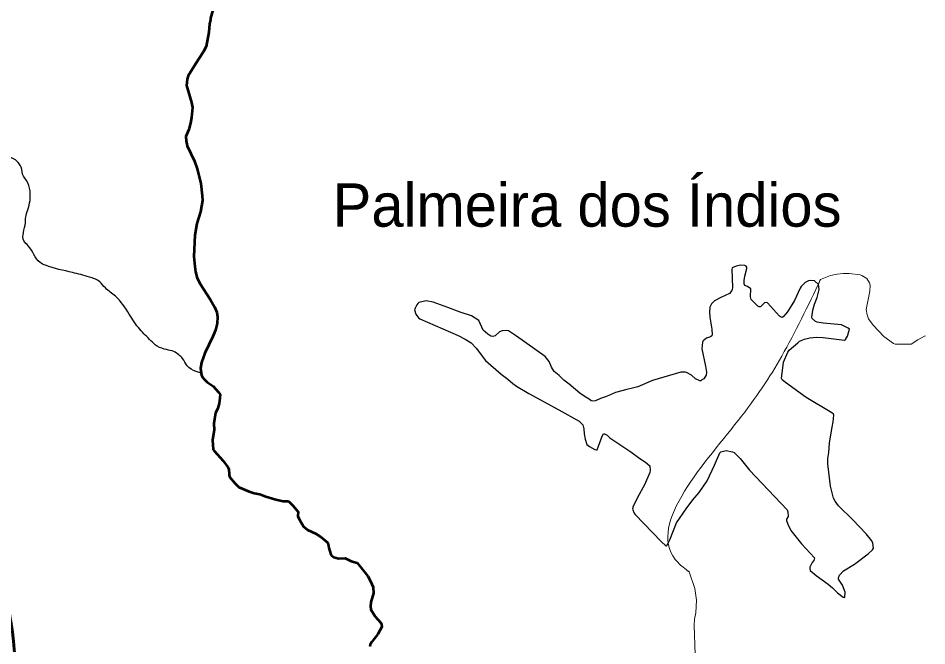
# Model space of a CAD drawing. Extents: x -1643653 to 4543381, y 1624270 to 13878484.
# Drawn here: x 752066 to 762553, y 8956206 to 8963451 of the extents above; entities that cross this region are included whole.
import ezdxf

# ---------------------------------------------------------------- set-up
doc = ezdxf.new("R2010")
doc.units = 0
doc.header["$LTSCALE"] = 160
doc.linetypes.add('MEDIUM_DASHED', pattern=[4.5, 3, -1.5])
for name, color, linetype, lineweight in [('10', 7, 'MEDIUM_DASHED', 60), ('14', 7, 'Continuous', 13), ('21', 7, 'Continuous', 25), ('24', 7, 'Continuous', 25), ('60', 7, 'Continuous', 13)]:
    doc.layers.add(name, color=color, linetype=linetype, lineweight=lineweight)
doc.layers.add('41', color=7, linetype='Continuous')

msp = doc.modelspace()

# ---------------------------------------------------------------- linework, layer by layer
at = {"layer": '10'}
for points in [[(751718.9, 8957290.2), (751531.6, 8957712.2), (750995.8, 8957861.4), (750836, 8958259.9), (750739.1, 8958501.4), (750810.6, 8958803), (750701.7, 8959043.4), (750649.5, 8959158.5), (750585.8, 8959273.1), (750522.6, 8959379.2), (750416.4, 8959557.6), (750245.2, 8959714.4), (750142.1, 8959894), (750059.8, 8960037.4), (750424.3, 8960195.8), (750388.3, 8960341.7), (750306, 8960675.5), (749757.2, 8960933.4), (749694.4, 8961281.9), (749657.1, 8961488.8), (749737.2, 8961760.6), (749694.4, 8961975.8), (749670.2, 8962097.1), (749510.2, 8962210.1), (749537.7, 8962334), (749613.3, 8962675.1), (749758.5, 8963019.6), (749851.1, 8963363.7), (749964, 8963783.7), (750022.5, 8964223.4), (750164.5, 8964639.7), (750243.4, 8964871.2), (750497.6, 8964991.5), (750634.5, 8965199.3), (750728.3, 8965341.6), (750833.7, 8965482.3), (750858.4, 8965647), (750892.9, 8965877.2), (750782, 8966109.4), (750768.8, 8966340.9), (750760.8, 8966481.8), (750668.1, 8966638.3), (750791.2, 8966766.2), (750923.4, 8966903.6), (751072.8, 8966882.1), (751216.6, 8966934), (751537.1, 8967049.7), (751840, 8967247.2), (752179.1, 8967269.8), (752291, 8967277.3), (752403, 8967284.8), (752514.9, 8967292.2), (752738.7, 8967307.2), (752962.6, 8967322.1), (753186.4, 8967337), (753247.3, 8967341.1), (753307.9, 8967370.8), (753353.8, 8967411.3)], [(752064, 8949931.3), (752226.2, 8950099), (752371.1, 8950281.5), (752484, 8950494.8), (752727.4, 8950954.4), (752832, 8951444.1), (752990, 8951926.7), (753136.7, 8952374.9), (753359.2, 8952845.2), (753347.9, 8953290.8), (753342, 8953522.6), (753008.5, 8953646.6), (752804.9, 8953784.5), (752471.5, 8954010.4), (751900.3, 8953804.2), (751669.5, 8954179.5), (751384.3, 8954643.3), (752099.3, 8955128.6), (752064.4, 8955611.4), (752024.1, 8956168.6), (751963.7, 8956738.7), (751718.9, 8957290.2)]]:
    msp.add_open_spline(points, degree=3, dxfattribs=at)
at = {"layer": '14'}
for points in [[(762539, 8959785.5), (762526.5, 8959782.1), (762447.5, 8959737.2), (762371.9, 8959688.1), (762188, 8959687.4), (762169, 8959695.8), (762058.2, 8959775.3), (761932.6, 8959909.4), (761880.9, 8959981.3), (761863.6, 8960025), (761852.7, 8960090.2), (761896.3, 8960301.7), (761898.2, 8960370.1), (761891.8, 8960394.3), (761858.6, 8960446.3), (761803.1, 8960482.1), (761785, 8960487.6), (761657.6, 8960503.3), (761588.8, 8960503.3), (761520, 8960497.3), (761442.8, 8960481.4), (761326.7, 8960433.8), (761317.3, 8960424.7), (761303.1, 8960378.2)], [(759805, 8957070.3), (759809.7, 8957060.9), (759876.2, 8956866.7), (759896, 8956733.5), (759886, 8956587.7), (759873.4, 8956514.6), (759867.3, 8956445.9), (759879.8, 8956106.2)]]:
    msp.add_lwpolyline(points, dxfattribs=at)
msp.add_spline([(761326.7, 8960433.8), (760878.8, 8959550), (760374.9, 8958805.9), (759682, 8957166.3), (759809.7, 8957060.9)], degree=3, dxfattribs=at)
at = {"layer": '21'}
for points in [[(760406.9, 8960599.4), (760351.2, 8960587.4), (760306.3, 8960567.9), (760304.1, 8960553.3), (760309.9, 8960343.7), (760307.6, 8960319.4), (760302.3, 8960306.5), (760277, 8960272.3), (760173.9, 8960227.9), (760102, 8960186.9), (760066.3, 8960155.5), (760048.5, 8960114.9), (760043.8, 8960055.7), (760047.2, 8959999.8), (760070.9, 8959859.8), (760077.3, 8959796.6), (760071.9, 8959782.9), (760055.5, 8959771.5), (760010.4, 8959755.9), (759970.5, 8959727.7), (759962.7, 8959712), (759957.3, 8959636.2), (760000.3, 8959433.2), (760011.1, 8959366.6), (760007.5, 8959329.7), (759980.1, 8959288.4), (759957.5, 8959276), (759943.8, 8959263.8), (759943.8, 8959263.8), (759931.4, 8959264.6), (759884.8, 8959286.2), (759838.1, 8959329.8), (759780.4, 8959363), (759763.1, 8959366.1), (759715.1, 8959363.1), (759387.5, 8959268.5), (759215.8, 8959195.5), (759154.3, 8959182.2), (759089.3, 8959164.5)], [(761303.1, 8960378.2), (761256.6, 8960420.7), (761211, 8960424.4), (761189, 8960420), (761148.3, 8960398.4), (761101, 8960352.7), (761089.5, 8960334.7), (761027.1, 8960191.2), (760943.1, 8960062.8), (760896.2, 8960002.8), (760882, 8959997.4), (760865.7, 8960003.5), (760853.2, 8960013.2), (760749.8, 8960127.6), (760712.2, 8960164.5), (760701.2, 8960167.6), (760679.8, 8960164.2), (760632.4, 8960121), (760616.8, 8960117.8), (760603.7, 8960126.1), (760526.3, 8960205.6), (760516.4, 8960233.9), (760520.7, 8960327.1), (760483.2, 8960353), (760453.9, 8960367.2), (760443.7, 8960384.1), (760443.7, 8960422.2), (760450.8, 8960474.1), (760476.4, 8960562.9), (760474.8, 8960577.8), (760467.9, 8960589.4), (760454.3, 8960595.3), (760406.9, 8960599.4)], [(761456.2, 8958896.2), (761158.8, 8959073.4), (760923.1, 8959244.1), (760881.8, 8959278.4), (760874.4, 8959292.7), (760897, 8959480.3), (760948.2, 8959595.3), (760963.9, 8959617.7), (761063.1, 8959703.5), (761082.5, 8959724.5), (761142.1, 8959747.5), (761202.2, 8959763.2), (761279.4, 8959770.2), (761356.4, 8959765.7), (761602.1, 8959732.9), (761613.8, 8959740.5), (761636.1, 8959780.9), (761661.5, 8959862.7), (761646.6, 8959874.6), (761567.3, 8959909.9), (761356.6, 8959929.5), (761288, 8959941.5), (761269.3, 8959950.7), (761230.4, 8959983.8), (761227.4, 8960000.2), (761237.8, 8960082), (761258.1, 8960151), (761288.7, 8960228.4), (761310.4, 8960320.3), (761303.1, 8960378.2)], [(756667.8, 8960142.8), (756646.1, 8960103.2), (756641.9, 8960082.9), (756655.4, 8960034.6), (756685.1, 8959993.4), (756700.1, 8959979.2), (757143.4, 8959788.8), (757225.5, 8959744.8), (757292.5, 8959702.4), (757351, 8959642), (757458.4, 8959500.5), (757638.5, 8959341.8), (757717.9, 8959284.2), (757774.1, 8959233.8), (757815.6, 8959204.4), (757958.2, 8959117.6), (758306, 8958929.9), (758539.4, 8958798.4), (758570.9, 8958770.5), (758581.6, 8958755.2), (758594, 8958710.9), (758597.7, 8958651.4), (758608.3, 8958591.8), (758630.7, 8958530.3), (758658.3, 8958506.6), (758722.6, 8958472.6), (758739.5, 8958467.4), (758749.1, 8958469.2), (758804.9, 8958627.7), (758819.6, 8958652.9), (758832.5, 8958653.7), (758862.6, 8958638.9), (758895.1, 8958607.2), (759137.6, 8958446.3), (759240.8, 8958367.8), (759305.9, 8958326.1), (759355.4, 8958284.4), (759361.1, 8958229.7), (759356.1, 8958207.5), (759296.4, 8958064.8), (759214.4, 8957916.7), (759160.7, 8957806.5), (759158.7, 8957795.2)], [(757025.3, 8960111), (756856.9, 8960173.6), (756774.4, 8960189), (756690.4, 8960169.5), (756676.8, 8960159.2), (756667.8, 8960142.8)], [(757384.3, 8959963), (757296.5, 8960017), (757165.6, 8960058.9), (757025.3, 8960111)], [(759089.3, 8959164.5), (758959.7, 8959128.9), (758856.5, 8959082.7), (758786.4, 8959061), (758729.8, 8959035.8), (758696.2, 8959030.6), (758679.5, 8959033.6), (758657.5, 8959052.8), (758608.3, 8959079.4), (758549.1, 8959121.3), (758427, 8959226.7), (758365.1, 8959274.5), (758308.6, 8959327.6), (758250.8, 8959371), (758222.4, 8959421.7), (758194.1, 8959488.8), (758147.7, 8959547.5), (757819.2, 8959780.1), (757726.2, 8959841.5), (757701.7, 8959847.4), (757651.1, 8959840.7), (757620.3, 8959829.3), (757571.8, 8959784.6), (757543.6, 8959777.7), (757522.3, 8959779.8), (757486.6, 8959802), (757431.8, 8959850.2), (757384.3, 8959963)], [(761460.2, 8958729), (761471.4, 8958793.2), (761478, 8958868), (761475.3, 8958881.2), (761456.2, 8958896.2)], [(761699.8, 8957660.8), (761534.4, 8957820.5), (761494.3, 8957876.1), (761476.7, 8957908.7), (761441.7, 8958050.3), (761410.2, 8958307.4), (761410.3, 8958367.7), (761421.6, 8958439.5), (761428.9, 8958549.5), (761460.2, 8958729)], [(759588.1, 8957430.5), (759665.6, 8957627.1), (759774.1, 8957789.3), (759851, 8957889.6), (759926.4, 8957977.2), (760019.3, 8958109.5), (760103.6, 8958290.5), (760163.1, 8958434.3), (760177, 8958444.1), (760236, 8958459.9), (760236, 8958459.9), (760311.5, 8958445.7), (760328.1, 8958437.3), (760399.4, 8958368.9), (760505.5, 8958234.5), (760941.1, 8957774.4), (760949.2, 8957754.5), (760953.1, 8957699.6), (760934.3, 8957666.8), (760932.5, 8957654.1), (760946.9, 8957611.2), (760983.8, 8957536.8), (761107.8, 8957384.2), (761255, 8957220.4), (761250.7, 8957192.7), (761230.3, 8957168.3), (761203.2, 8957115.4), (761200.8, 8957095.3), (761208, 8957075.8), (761277.5, 8957017.6), (761412.8, 8956919.4), (761466, 8956875.3), (761523.6, 8956817.2), (761588.2, 8956767.8), (761600.9, 8956762.8), (761607.8, 8956766.9), (761610.8, 8956824.1), (761578.4, 8956906.9), (761533.3, 8956976.3), (761532.5, 8956989.4), (761545, 8957020.8), (761589.6, 8957073.6), (761719.9, 8957149.7), (761874.4, 8957269.1), (761925.5, 8957315.7), (761936.7, 8957332.9), (761927.8, 8957389.9), (761916.5, 8957416.7), (761854.4, 8957499), (761699.8, 8957660.8)], [(759158.7, 8957795.2), (759156.5, 8957782.8), (759174.7, 8957739.3), (759187.4, 8957722), (759486.6, 8957410.7), (759541.3, 8957360.2), (759547, 8957358.6), (759554, 8957364.5), (759569.1, 8957391.3), (759588.1, 8957430.5)]]:
    msp.add_lwpolyline(points, dxfattribs=at)
at = {"layer": '24', "lineweight": 53}
for points in [[(754324.4, 8963585.7), (754286.8, 8963450), (754285.7, 8963432), (754273.9, 8963387.1), (754266, 8963290.7), (754236.9, 8963123.5), (754201.7, 8963057.3), (754114.6, 8962926), (754027.8, 8962785.2), (754016.9, 8962748.7), (754010.6, 8962674.3), (754066.2, 8962478), (754076.2, 8962418.6), (754066.8, 8962303.7), (754054.9, 8962239.9), (754034.7, 8962164.2), (754002.5, 8962083.6), (754003.6, 8962036.3), (754018, 8961976.9), (754099.6, 8961801.3), (754131.9, 8961713.6), (754174.2, 8961542.5), (754191.4, 8961398.6), (754193.2, 8961347.2), (754168.7, 8961215.5), (754129.2, 8961079.8), (754106, 8960948.1), (754094.1, 8960701.2), (754103.1, 8960586), (754113, 8960522.2)], [(754113, 8960522.2), (754133.2, 8960450.2), (754164.6, 8960385.9), (754285.4, 8960201), (754333.3, 8960119.1), (754358.5, 8960059.1), (754366.7, 8960003.6), (754361.1, 8959927.4), (754342.9, 8959851.5), (754312.2, 8959776.4), (754218.7, 8959583.9), (754182.3, 8959476.4), (754169.4, 8959412.5), (754180.9, 8959330), (754188.6, 8959309.7), (754216.4, 8959278.5), (754249.1, 8959251.2), (754317.6, 8959205.1), (754378.4, 8959135.3), (754396.6, 8959107.3), (754395.3, 8959068.2), (754385.8, 8959005.2), (754369.7, 8958949.7), (754345.2, 8958889.9), (754331, 8958822.6), (754326, 8958771), (754328.4, 8958699.2), (754310.7, 8958580.2), (754315.6, 8958473.5), (754326.5, 8958456.4), (754433.4, 8958343.3), (754486.5, 8958269.1), (754495.6, 8958248.3), (754500.9, 8958184.1), (754506.9, 8958158.4), (754569.5, 8958079.4), (754610.9, 8958038.6)], [(754610.9, 8958038.6), (754610.9, 8958038.6), (754731.2, 8957987.7), (754791.1, 8957970), (754854.6, 8957958.1), (754922.6, 8957930.3), (755038.2, 8957895.5), (755123.8, 8957875.9), (755185.9, 8957875.1)], [(755185.9, 8957875.1), (755238.8, 8957821.3), (755295.4, 8957755.3), (755298.8, 8957744.7), (755293, 8957714.3), (755295, 8957700.2), (755316.4, 8957655.1), (755359, 8957583.6), (755405.6, 8957545), (755497.6, 8957501.2), (755563.5, 8957459.9), (755635.5, 8957398.1), (755644, 8957381.6), (755650.3, 8957338.2), (755674.1, 8957259.6), (755682.8, 8957247.8), (755709.3, 8957231.1), (755761.1, 8957215.6), (755838.8, 8957216.3), (755909.4, 8957183.9), (755979.1, 8957165.2)], [(755979.1, 8957165.2), (756099.8, 8957011.9), (756133.3, 8956953.6), (756164.7, 8956883.8)], [(756164.7, 8956883.8), (756167.7, 8956814.9), (756135.2, 8956708.9), (756132.8, 8956661.9), (756136.2, 8956626.4), (756187.9, 8956545.8), (756252.7, 8956472.7), (756258.8, 8956454.4), (756261.3, 8956424.2), (756215.1, 8956340.9), (756146.2, 8956251.2), (756128.1, 8956221.2), (756124, 8956199.7)]]:
    msp.add_lwpolyline(points, dxfattribs=at)
at = {"layer": '24'}
for points in [[(754324.4, 8963585.7), (754286.8, 8963450), (754285.7, 8963432), (754273.9, 8963387.1), (754266, 8963290.7), (754236.9, 8963123.5), (754201.7, 8963057.3), (754114.6, 8962926), (754027.8, 8962785.2), (754016.9, 8962748.7), (754010.6, 8962674.3), (754066.2, 8962478), (754076.2, 8962418.6), (754066.8, 8962303.7), (754054.9, 8962239.9), (754034.7, 8962164.2), (754002.5, 8962083.6), (754003.6, 8962036.3), (754018, 8961976.9), (754099.6, 8961801.3), (754131.9, 8961713.6), (754174.2, 8961542.5), (754191.4, 8961398.6), (754193.2, 8961347.2), (754168.7, 8961215.5), (754129.2, 8961079.8), (754106, 8960948.1), (754094.1, 8960701.2), (754103.1, 8960586), (754113, 8960522.2)], [(754113, 8960522.2), (754133.2, 8960450.2), (754164.6, 8960385.9), (754285.4, 8960201), (754333.3, 8960119.1), (754358.5, 8960059.1), (754366.7, 8960003.6), (754361.1, 8959927.4), (754342.9, 8959851.5), (754312.2, 8959776.4), (754218.7, 8959583.9), (754182.3, 8959476.4), (754169.4, 8959412.5), (754180.9, 8959330), (754188.6, 8959309.7), (754216.4, 8959278.5), (754249.1, 8959251.2), (754317.6, 8959205.1), (754378.4, 8959135.3), (754396.6, 8959107.3), (754395.3, 8959068.2), (754385.8, 8959005.2), (754369.7, 8958949.7), (754345.2, 8958889.9), (754331, 8958822.6), (754326, 8958771), (754328.4, 8958699.2), (754310.7, 8958580.2), (754315.6, 8958473.5), (754326.5, 8958456.4), (754433.4, 8958343.3), (754486.5, 8958269.1), (754495.6, 8958248.3), (754500.9, 8958184.1), (754506.9, 8958158.4), (754569.5, 8958079.4), (754610.9, 8958038.6)], [(754610.9, 8958038.6), (754610.9, 8958038.6), (754731.2, 8957987.7), (754791.1, 8957970), (754854.6, 8957958.1), (754922.6, 8957930.3), (755038.2, 8957895.5), (755123.8, 8957875.9), (755185.9, 8957875.1)], [(755185.9, 8957875.1), (755238.8, 8957821.3), (755295.4, 8957755.3), (755298.8, 8957744.7), (755293, 8957714.3), (755295, 8957700.2), (755316.4, 8957655.1), (755359, 8957583.6), (755405.6, 8957545), (755497.6, 8957501.2), (755563.5, 8957459.9), (755635.5, 8957398.1), (755644, 8957381.6), (755650.3, 8957338.2), (755674.1, 8957259.6), (755682.8, 8957247.8), (755709.3, 8957231.1), (755761.1, 8957215.6), (755838.8, 8957216.3), (755909.4, 8957183.9), (755979.1, 8957165.2)], [(755979.1, 8957165.2), (756099.8, 8957011.9), (756133.3, 8956953.6), (756164.7, 8956883.8)], [(756164.7, 8956883.8), (756167.7, 8956814.9), (756135.2, 8956708.9), (756132.8, 8956661.9), (756136.2, 8956626.4), (756187.9, 8956545.8), (756252.7, 8956472.7), (756258.8, 8956454.4), (756261.3, 8956424.2), (756215.1, 8956340.9), (756146.2, 8956251.2), (756128.1, 8956221.2), (756124, 8956199.7)]]:
    msp.add_lwpolyline(points, dxfattribs=at)
msp.add_spline([(754168.1, 8959356.7), (754118.5, 8959373.3), (754015.9, 8959439.5), (753963, 8959522.3), (753920, 8959565.3), (753863.7, 8959601.7), (753777.7, 8959624.9), (753671.8, 8959664.6), (753599, 8959727.5), (753470, 8959860), (753347.6, 8960035.4), (753188.7, 8960240.7), (753072.9, 8960336.7), (753006.8, 8960409.6), (752887.7, 8960462.5), (752692.4, 8960515.5), (752381.4, 8960598.3), (752318.6, 8960631.4), (752182.9, 8960823.4), (752133.3, 8960879.7), (752149.8, 8961088.3), (752153.1, 8961154.5), (752176.3, 8961240.6), (752202.8, 8961346.5), (752202.8, 8961459.1), (752163.1, 8961578.2), (752126.7, 8961627.9), (752100.2, 8961730.6), (752067.1, 8961783.5), (752020.8, 8961823.2), (751842.1, 8961922.6), (751815.6, 8962002), (751828.9, 8962035.1), (751891.7, 8962194.1), (751891.7, 8962247), (751799.1, 8962392.7), (751723, 8962475.5), (751686.6, 8962551.6), (751673.4, 8962674.1), (751680, 8962710.5), (751646.7, 8962746), (751629.2, 8962814.3), (751582.4, 8962896.2), (751541.5, 8962972.3), (751516.1, 8963036.6), (751490.8, 8963138), (751498.6, 8963270.7), (751510.3, 8963338.9), (751566.8, 8963485.2), (751623.3, 8963580.8), (751638.9, 8963627.6), (751638.9, 8963670.5), (751613.6, 8963762.2), (751561, 8963914.3), (751555.1, 8963990.3), (751566.8, 8964163.9), (751545.4, 8964241.9), (751500.6, 8964314.1), (751401.2, 8964419.4), (751358.3, 8964503.3), (751350.5, 8964659.3), (751381.7, 8964780.2), (751408.9, 8964864.1), (751405, 8964942.1), (751391.4, 8965002.6), (751327.1, 8965100.1), (751223.8, 8965226.9), (751149.7, 8965359.5), (751110.7, 8965523.3), (751102.9, 8965618.9), (751071.8, 8965913.4), (751038.6, 8966215.7), (751023, 8966471), (751017.2, 8966644)], degree=3, dxfattribs=at)
at = {"layer": '60', "lineweight": 25}
msp.add_spline([(814781, 9009175.5), (814787.2, 9009173.4), (814796.9, 9009173.4), (814799.4, 9009172.4), (814805.1, 9009174.5), (814805.6, 9009176.5), (814811.7, 9009179.5), (814811.7, 9009179.5), (814801.5, 9009181), (814790.7, 9009181.5), (814784.1, 9009183.1), (814777.4, 9009185.1), (814778.4, 9009175.5)], degree=3, dxfattribs=at)

# ---------------------------------------------------------------- texts
at = {"layer": '41'}
msp.add_text('Palmeira dos Índios', height=500, dxfattribs=at).set_placement((755696.3, 8961044.2))

doc.saveas('drawing.dxf')
